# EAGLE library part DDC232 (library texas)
32-Channel, Current-Input Analog-to-Digital Converter Source: http://focus.ti.com/lit/ds/symlink/ddc232.pdf
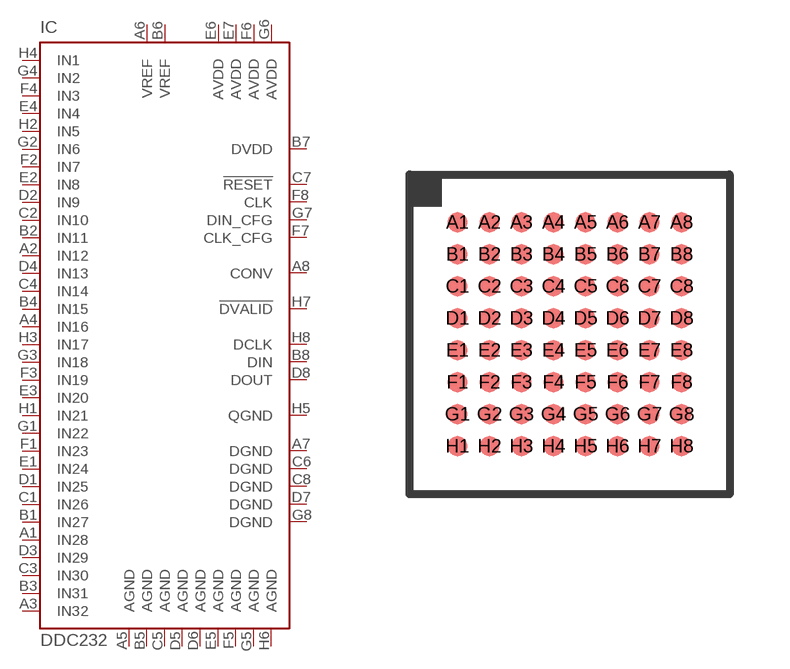
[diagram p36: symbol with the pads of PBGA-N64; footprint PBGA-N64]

Designator prefix IC

## DDC232 (MPN: DDC232CGXGR; OC_FARNELL: unknown; OC_NEWARK: 18M7216)  [PBGA-N64]
A1  IN28  in
A2  IN12  in
A3  IN32  in
A4  IN16  in
A5  AGND  pwr
A6  VREF  pas
A7  DGND  pwr
A8  CONV  in
B1  IN27  in
B2  IN11  in
B3  IN31  in
B4  IN15  in
B5  AGND  pwr
B6  VREF  pas
B7  DVDD  pwr
B8  DIN  in
C1  IN26  in
C2  IN10  in
C3  IN30  in
C4  IN14  in
C5  AGND  pwr
C6  DGND  pwr
C7  !RESET  in
C8  DGND  pwr
D1  IN25  in
D2  IN9  in
D3  IN29  in
D4  IN13  in
D5  AGND  pwr
D6  AGND  pwr
D7  DGND  pwr
D8  DOUT  out
E1  IN24  in
E2  IN8  in
E3  IN20  in
E4  IN4  in
E5  AGND  pwr
E6  AVDD  pwr
E7  AVDD  pwr
F1  IN23  in
F2  IN7  in
F3  IN19  in
F4  IN3  in
F5  AGND  pwr
F6  AVDD  pwr
F7  CLK_CFG  in
F8  CLK  in
G1  IN22  in
G2  IN6  in
G3  IN18  in
G4  IN2  in
G5  AGND  pwr
G6  AVDD  pwr
G7  DIN_CFG  in
G8  DGND  pwr
H1  IN21  in
H2  IN5  in
H3  IN17  in
H4  IN1  in
H5  QGND  pwr
H6  AGND  pwr
H7  !DVALID  out
H8  DCLK  in

## Footprint PBGA-N64 (pad centres in mm)
GXG (S-PBGA-N64 Source: http://focus.ti.com/lit/ds/symlink/ddc232.pdf
smd 0.5 x 0.5: A1 -2.8,2.8; A2 -2,2.8; A3 -1.2,2.8; A4 -0.4,2.8; A5 0.4,2.8; A6 1.2,2.8; A7 2,2.8; A8 2.8,2.8; B1 -2.8,2; B2 -2,2; B3 -1.2,2; B4 -0.4,2; B5 0.4,2; B6 1.2,2; B7 2,2; B8 2.8,2; C1 -2.8,1.2; C2 -2,1.2; C3 -1.2,1.2; C4 -0.4,1.2; C5 0.4,1.2; C6 1.2,1.2; C7 2,1.2; C8 2.8,1.2; D1 -2.8,0.4; D2 -2,0.4; D3 -1.2,0.4; D4 -0.4,0.4; D5 0.4,0.4; D6 1.2,0.4; D7 2,0.4; D8 2.8,0.4; E1 -2.8,-0.4; E2 -2,-0.4; E3 -1.2,-0.4; E4 -0.4,-0.4; E5 0.4,-0.4; E6 1.2,-0.4; E7 2,-0.4; E8 2.8,-0.4; F1 -2.8,-1.2; F2 -2,-1.2; F3 -1.2,-1.2; F4 -0.4,-1.2; F5 0.4,-1.2; F6 1.2,-1.2; F7 2,-1.2; F8 2.8,-1.2; G1 -2.8,-2; G2 -2,-2; G3 -1.2,-2; G4 -0.4,-2; G5 0.4,-2; G6 1.2,-2; G7 2,-2; G8 2.8,-2; H1 -2.8,-2.8; H2 -2,-2.8; H3 -1.2,-2.8; H4 -0.4,-2.8; H5 0.4,-2.8; H6 1.2,-2.8; H7 2,-2.8; H8 2.8,-2.8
